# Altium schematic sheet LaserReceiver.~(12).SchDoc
size A; DocumentNumber: 4; SheetNumber: 4; SheetTotal: 6
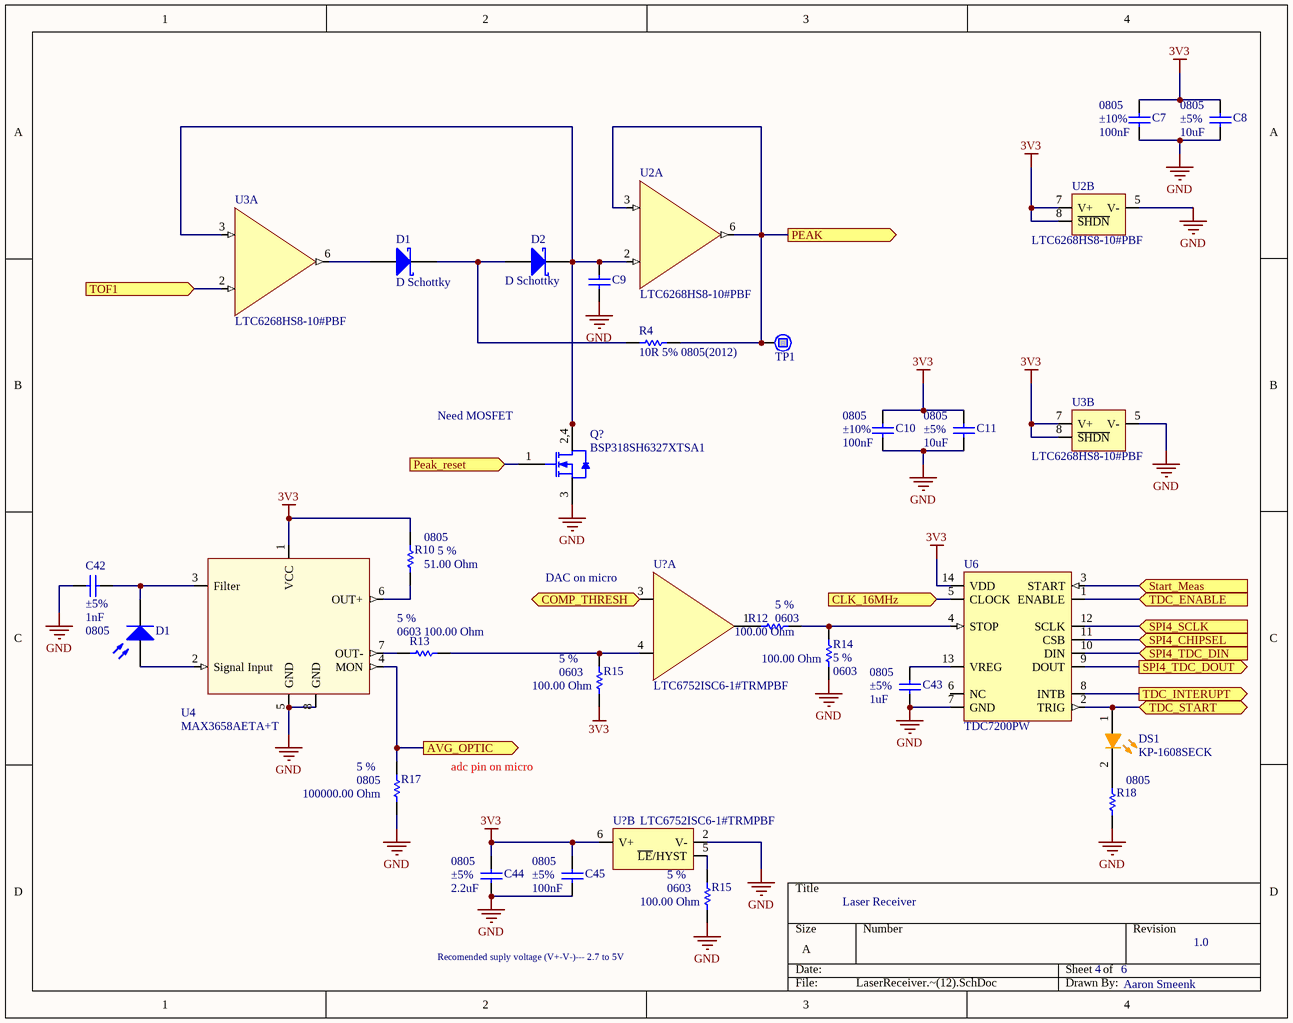
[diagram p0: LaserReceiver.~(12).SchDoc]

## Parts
(Parts that share a designator on the sheet are numbered #1, #2 ... from top to bottom, then left to right.)
C7  value 100nF  Case-EIA: 0805  Tolerance: ±10%  [CAPC0805(2012)100_N]  (hidden comment: CAP 100nF 6.3V 0805(2012))
C8  value 10uF  Case-EIA: 0805  Tolerance: ±5%  [CAPC0805(2012)145_N]  (hidden comment: CAP 10uF 6.3V 0805(2012))
C9  CAP 1nF 6.3V 0805(2012)  [CAPC0805(2012)100_M]  (value not drawn)
C10  value 100nF  Case-EIA: 0805  Tolerance: ±10%  [CAPC0805(2012)100_N]  (hidden comment: CAP 100nF 6.3V 0805(2012))
C11  value 10uF  Case-EIA: 0805  Tolerance: ±5%  [CAPC0805(2012)145_N]  (hidden comment: CAP 10uF 6.3V 0805(2012))
C42  value 1nF  Tolerance: ±5%  Case-EIA: 0805  [CAPC0805(2012)100_M]  (hidden comment: CAP 1nF 6.3V 0805(2012))
C43  value 1uF  Tolerance: ±5%  Case-EIA: 0805  [CAPC0805(2012)100_M]  (hidden comment: CAP 1uF 6.3V 0805(2012))
C44  value 2.2uF  Tolerance: ±5%  Case-EIA: 0805  [CAPC0805(2012)100_M]  (hidden comment: CAP 2.2uF 6.3V 0805(2012))
C45  value 100nF  Tolerance: ±5%  Case-EIA: 0805  [CAPC0805(2012)100_M]  (hidden comment: CAP 100nF 6.3V 0805(2012))
D1#1  D Schottky  [BAT6402VH6327XTSA1--DIOM1208X06N]
D1#2  Photo Sen  [PIN2]  (value not drawn)
D2  D Schottky  [BAT6402VH6327XTSA1--DIOM1208X06N]
DS1  KP-1608SECK  [KING-0603LED_ORANGE_V]
Q?  BSP318SH6327XTSA1
R4  10R 5% 0805(2012)  [RESC0805(2012)_L]
R10  value 51.00 Ohm  Tolerance: 5 %  Case-EIA: 0805  [RESC0805(2012)_N]  (hidden comment: 51R 5% 0805(2012))
R12  value 100.00 Ohm  Tolerance: 5 %  Case-EIA: 0603  [RESC0603(1608)_L]  (hidden comment: 100R 5% 0603(1608))
R13  value 100.00 Ohm  Tolerance: 5 %  Case-EIA: 0603  [RESC0603(1608)_L]  (hidden comment: 100R 5% 0603(1608))
R14  value 100.00 Ohm  Tolerance: 5 %  Case-EIA: 0603  [RESC0603(1608)_L]  (hidden comment: 100R 5% 0603(1608))
R15#1  value 100.00 Ohm  Tolerance: 5 %  Case-EIA: 0603  [RESC0603(1608)_L]  (hidden comment: 100R 5% 0603(1608))
R15#2  value 100.00 Ohm  Tolerance: 5 %  Case-EIA: 0603  [RESC0603(1608)_L]  (hidden comment: 100R 5% 0603(1608))
R17  value 100000.00 Ohm  Tolerance: 5 %  Case-EIA: 0805  [RESC0805(2012)_L]  (hidden comment: 100K 5% 0805(2012))
R18  Case-EIA: 0805  [RESC0805(2012)_N]  (hidden comment: 51R 5% 0805(2012))
TP1  TestPoint  [TestPoint]  (value not drawn)
U2  LTC6268HS8-10#PBF  [LTC6268HS8-10#PBF--SOIC127P600X175-8N]  (parts A,B of 2)
U3  LTC6268HS8-10#PBF  [LTC6268HS8-10#PBF--SOIC127P600X175-8N]  (parts A,B of 2)
U4  MAX3658AETA+T  [MAX3658AETA+T--QFN0P300X300X80_HS-9N]
U6  TDC7200PW  [TDC7200PW--TSOP65P640X120-14N]
U?#1  LTC6752ISC6-1#TRMPBF  (part A of 2)
U?#2  LTC6752ISC6-1#TRMPBF  (part B of 2)

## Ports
AVG_OPTIC (out), CLK_16MHz (in), COMP_THRESH (in), PEAK (out), Peak_reset (in), SPI4_CHIPSEL (in), SPI4_SCLK (in), SPI4_TDC_DIN (in), SPI4_TDC_DOUT (out), Start_Meas (in), TDC_ENABLE (in), TDC_INTERUPT (out), TDC_START, TOF1 (in)

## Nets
3V3: C7.2 C8.2 C10.2 C11.2 C44.2 C45.2 R10.2 R15#1.1 U2.7(V+) U2.8(~{SHDN}) U3.7(V+) U3.8(~{SHDN}) U4.1(VCC) U6.14(VDD) U?#2.6(V+)
GND: C7.1 C8.1 C9.1 C10.1 C11.1 C42.1 C43.1 C44.1 C45.1 Q?.3(S) R14.2 R15#2.1 R17.1 R18.1 U2.5(V-) U3.5(V-) U4.5(GND) U4.8(GND) U4.9(PAD) U6.7(GND) U?#2.2(V-)
AVG_OPTIC: R17.2 U4.4(MON) ; port AVG_OPTIC
CLK_16MHz: U6.5(CLOCK) ; port CLK_16MHz
COMP_THRESH: U?#1.3(IN+) ; port COMP_THRESH
PEAK: R4.2 TP1.1 U2.3(IN+) U2.6(OUT) ; port PEAK
Peak_reset: Q?.1(G) ; port Peak_reset
SPI4_CHIPSEL: U6.11(CSB) ; port SPI4_CHIPSEL
SPI4_SCLK: U6.12(SCLK) ; port SPI4_SCLK
SPI4_TDC_DIN: U6.10(DIN) ; port SPI4_TDC_DIN
SPI4_TDC_DOUT: U6.9(DOUT) ; port SPI4_TDC_DOUT
Start_Meas: U6.3(START) ; port Start_Meas
TDC_ENABLE: U6.1(ENABLE) ; port TDC_ENABLE
TDC_INTERUPT: U6.8(INTB) ; port TDC_INTERUPT
TDC_START: DS1.1(A) U6.2(TRIG) ; port TDC_START
TOF1: U3.2(IN-) ; port TOF1
NetC9_2: C9.2 D2.2(K) Q?.2(D) Q?.4(D) U2.2(IN-) U3.3(IN+)
NetC42_2: C42.2 D1#2.2(K) U4.3(Filter)
NetC43_2: C43.2 U6.13(VREG)
NetD1#1_1: D1#1.1(A) U3.6(OUT)
NetD1#1_2: D1#1.2(K) D2.1(A) R4.1
NetD1#2_1: D1#2.1(A) U4.2(Signal_Input)
NetDS1_2: DS1.2(K) R18.2
NetR10_1: R10.1 U4.6(OUT+)
NetR12_1: R12.1 R14.1 U6.4(STOP)
NetR12_2: R12.2 U?#1.1(OUT)
NetR13_1: R13.1 U4.7(OUT-)
NetR13_2: R13.2 R15#1.2 U?#1.4(IN-)
NetR15#2_2: R15#2.2 U?#2.5(~{LE}/HYST)

Not connected (* = marked no-connect by the designer): U6 6(NC)

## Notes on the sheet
- (near Q?) Need MOSFET
- (near U?#1) DAC on micro
- adc pin on micro
- Laser Receiver
- Recomended suply voltage (V+-V-)--- 2.7 to 5V
- 4
- 6
- 1.0
- Aaron Smeenk

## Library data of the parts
C7 C10 = CMP-1036-04391-1: CAP 100nF 6.3V ±10% 0805 (2012 Metric) Thickness 1mm SMD; Case-Metric: 2012
C8 C11 = CMP-1036-04781-1: CAP 10uF 6.3V ±5% 0805 (2012 Metric) Thickness 1.45mm SMD; Case-Metric: 2012
C9 = CMP-1036-02947-1: CAP 1nF 6.3V Â±5% 0805 (2012 Metric) Thickness 1mm SMD; Case-Metric: 2012; Case-EIA: 0805
C42 = CMP-1036-02947-1: CAP 1nF 6.3V ±5% 0805 (2012 Metric) Thickness 1mm SMD; Case-Metric: 2012
C43 = CMP-1036-02947-1: CAP 1uF 6.3V ±5% 0805 (2012 Metric) Thickness 1mm SMD; Case-Metric: 2012
C44 = CMP-1036-02947-1: CAP 2.2unF 6.3V ±5% 0805 (2012 Metric) Thickness 1mm SMD; Case-Metric: 2012
C45 = CMP-1036-02947-1: CAP 100nF 6.3V ±5% 0805 (2012 Metric) Thickness 1mm SMD; Case-Metric: 2012
D1#1 D2 = D Schottky: Schottky Diode
D1#2 = Photo Sen: Photosensitive Diode
DS1 = CMP-0404-00002-1: LED, SMT, 0603(1608), 1.1mm thickness, Orange; Manufacturer: Kingbright; Power Dissipation: 75 mW; Packing Type: 2000 pcs / reel; Reverse Voltage: 5 V; Forward Current: 30 mA
Q? = BSP318SH6327XTSA1: MOSFET N-Ch 60V 2.6A SOT-223-3
R4 = CMP-1013-00026-1: 10R 0.125W 5% 0805 (2012 Metric)  SMD; Value: 10.00 Ohm; Case-EIA: 0805; Case-Metric: 2012
R10 = CMP-1013-00043-1: 51R 0.125W 5% 0805 (2012 Metric)  SMD; Case-Metric: 2012
R12-R14 R15#1 R15#2 = CMP-1012-00050-1: 100R 0.1W 5% 0603 (1608 Metric)  SMD; Case-Metric: 1608
R17 = CMP-1013-00122-1: 100K 0.125W 5% 0805 (2012 Metric)  SMD; Case-Metric: 2012
R18 = CMP-1013-00043-1: 51R 0.125W 5% 0805 (2012 Metric)  SMD; Value: 51.00 Ohm; Case-Metric: 2012
U2 U3 = LTC6268HS8-10#PBF: IC OPAMP 4GHZ SGL FET 8SOIC
U4 = MAX3658AETA+T: IC AMP TRANSIMPEDANCE 8-TDFN
U6 = TDC7200PW: STATIC ULTRASONIC FLOWMETER AF
U?#1 U?#2 = LTC6752ISC6-1#TRMPBF: IC COMP R-R CMOS 280MHZ SC70-6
